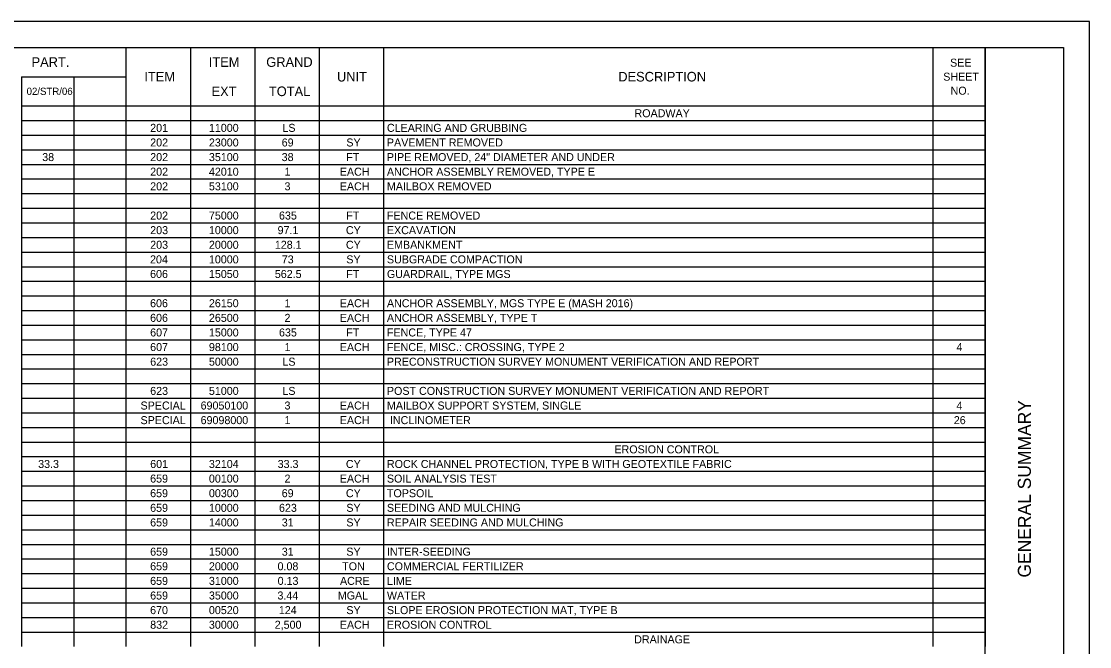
# Model space of a CAD drawing. Extents: x 0 to 34, y 0 to 22.
# Drawn here: x 13.53 to 34, y 10.02 to 22 of the extents above; entities that cross this region are included whole.
import ezdxf

# ---------------------------------------------------------------- set-up
doc = ezdxf.new("R2010")
doc.units = 0
for name, color, linetype in [('Default', 7, 'Continuous'), ('SH_Border', 7, 'Continuous'), ('SH_Cut_Line', 7, 'Continuous'), ('SH_Data', 7, 'Continuous')]:
    doc.layers.add(name, color=color, linetype=linetype)

msp = doc.modelspace()

# ---------------------------------------------------------------- linework, layer by layer
at = {"layer": 'Default'}
for p, q in [((13.53, 21.5), (15.535, 21.5)), ((15.535, 21.5), (32, 21.5)), ((15.535, 21.5), (15.535, 21.22)), ((16.769, 21.5), (16.769, 21.22)), ((18.003, 21.5), (18.003, 21.22)), ((19.237, 21.5), (19.237, 21.22)), ((20.471, 21.5), (20.471, 21.22)), ((30.997, 21.5), (30.997, 21.22)), ((32, 21.5), (32, 21.22)), ((15.535, 21.22), (15.535, 20.94)), ((16.769, 21.22), (16.769, 20.94)), ((18.003, 21.22), (18.003, 20.94)), ((19.237, 21.22), (19.237, 20.94)), ((20.471, 21.22), (20.471, 20.94)), ((30.997, 21.22), (30.997, 20.94)), ((32, 21.22), (32, 20.94)), ((13.53, 20.94), (15.535, 20.94)), ((13.53, 20.94), (13.53, 20.66)), ((14.533, 20.94), (14.533, 20.66)), ((15.535, 20.94), (15.535, 20.66)), ((16.769, 20.94), (16.769, 20.66)), ((18.003, 20.94), (18.003, 20.66)), ((19.237, 20.94), (19.237, 20.66)), ((20.471, 20.94), (20.471, 20.66)), ((30.997, 20.94), (30.997, 20.66)), ((32, 20.94), (32, 20.66)), ((13.53, 20.66), (13.53, 20.38)), ((14.533, 20.66), (14.533, 20.38)), ((15.535, 20.66), (15.535, 20.38)), ((16.769, 20.66), (16.769, 20.38)), ((18.003, 20.66), (18.003, 20.38)), ((19.237, 20.66), (19.237, 20.38)), ((20.471, 20.66), (20.471, 20.38)), ((30.997, 20.66), (30.997, 20.38)), ((32, 20.66), (32, 20.38)), ((13.53, 20.38), (15.535, 20.38)), ((13.53, 20.38), (13.53, 20.1)), ((14.533, 20.38), (14.533, 20.1)), ((15.535, 20.38), (32, 20.38)), ((15.535, 20.38), (15.535, 20.1)), ((16.769, 20.38), (16.769, 20.1)), ((18.003, 20.38), (18.003, 20.1)), ((19.237, 20.38), (19.237, 20.1)), ((20.471, 20.38), (20.471, 20.1)), ((30.997, 20.38), (30.997, 20.1)), ((32, 20.38), (32, 20.1)), ((13.53, 20.1), (15.535, 20.1)), ((13.53, 20.1), (13.53, 18.7)), ((14.533, 20.1), (14.533, 18.7)), ((15.535, 20.1), (32, 20.1)), ((15.535, 20.1), (15.535, 18.7)), ((16.769, 20.1), (16.769, 18.7)), ((18.003, 20.1), (18.003, 18.7)), ((19.237, 20.1), (19.237, 18.7)), ((20.471, 20.1), (20.471, 18.7)), ((30.997, 20.1), (30.997, 18.7)), ((32, 20.1), (32, 18.7)), ((13.53, 19.82), (15.535, 19.82)), ((15.535, 19.82), (32, 19.82)), ((13.53, 19.54), (15.535, 19.54)), ((15.535, 19.54), (32, 19.54)), ((13.53, 19.26), (15.535, 19.26)), ((15.535, 19.26), (32, 19.26)), ((13.53, 18.98), (15.535, 18.98)), ((15.535, 18.98), (32, 18.98)), ((13.53, 18.7), (15.535, 18.7)), ((13.53, 18.7), (13.53, 18.14)), ((14.533, 18.7), (14.533, 18.14)), ((15.535, 18.7), (32, 18.7)), ((15.535, 18.7), (15.535, 18.14)), ((16.769, 18.7), (16.769, 18.14)), ((18.003, 18.7), (18.003, 18.14)), ((19.237, 18.7), (19.237, 18.14)), ((20.471, 18.7), (20.471, 18.14)), ((30.997, 18.7), (30.997, 18.14)), ((32, 18.7), (32, 18.14)), ((13.53, 18.42), (15.535, 18.42)), ((15.535, 18.42), (32, 18.42)), ((13.53, 18.14), (15.535, 18.14)), ((13.53, 18.14), (13.53, 17.86)), ((14.533, 18.14), (14.533, 17.86)), ((15.535, 18.14), (32, 18.14)), ((15.535, 18.14), (15.535, 17.86)), ((16.769, 18.14), (16.769, 17.86)), ((18.003, 18.14), (18.003, 17.86)), ((19.237, 18.14), (19.237, 17.86)), ((20.471, 18.14), (20.471, 17.86)), ((30.997, 18.14), (30.997, 17.86)), ((32, 18.14), (32, 17.86)), ((13.53, 17.86), (15.535, 17.86)), ((13.53, 17.86), (13.53, 17.58)), ((14.533, 17.86), (14.533, 17.58)), ((15.535, 17.86), (32, 17.86)), ((15.535, 17.86), (15.535, 17.58)), ((16.769, 17.86), (16.769, 17.58)), ((18.003, 17.86), (18.003, 17.58)), ((19.237, 17.86), (19.237, 17.58)), ((20.471, 17.86), (20.471, 17.58)), ((30.997, 17.86), (30.997, 17.58)), ((32, 17.86), (32, 17.58)), ((13.53, 17.58), (15.535, 17.58)), ((13.53, 17.58), (13.53, 17.3)), ((14.533, 17.58), (14.533, 17.3)), ((15.535, 17.58), (32, 17.58)), ((15.535, 17.58), (15.535, 17.3)), ((16.769, 17.58), (16.769, 17.3)), ((18.003, 17.58), (18.003, 17.3)), ((19.237, 17.58), (19.237, 17.3)), ((20.471, 17.58), (20.471, 17.3)), ((30.997, 17.58), (30.997, 17.3)), ((32, 17.58), (32, 17.3)), ((13.53, 17.3), (15.535, 17.3)), ((13.53, 17.3), (13.53, 17.02)), ((14.533, 17.3), (14.533, 17.02)), ((15.535, 17.3), (32, 17.3)), ((15.535, 17.3), (15.535, 17.02)), ((16.769, 17.3), (16.769, 17.02)), ((18.003, 17.3), (18.003, 17.02)), ((19.237, 17.3), (19.237, 17.02)), ((20.471, 17.3), (20.471, 17.02)), ((30.997, 17.3), (30.997, 17.02)), ((32, 17.3), (32, 17.02)), ((13.53, 17.02), (15.535, 17.02)), ((13.53, 17.02), (13.53, 16.74)), ((14.533, 17.02), (14.533, 16.74)), ((15.535, 17.02), (32, 17.02)), ((15.535, 17.02), (15.535, 16.74)), ((16.769, 17.02), (16.769, 16.74)), ((18.003, 17.02), (18.003, 16.74)), ((19.237, 17.02), (19.237, 16.74)), ((20.471, 17.02), (20.471, 16.74)), ((30.997, 17.02), (30.997, 16.74)), ((32, 17.02), (32, 16.74)), ((13.53, 16.74), (15.535, 16.74)), ((13.53, 16.74), (13.53, 16.18)), ((14.533, 16.74), (14.533, 16.18)), ((15.535, 16.74), (32, 16.74)), ((15.535, 16.74), (15.535, 16.18)), ((16.769, 16.74), (16.769, 16.18)), ((18.003, 16.74), (18.003, 16.18)), ((19.237, 16.74), (19.237, 16.18)), ((20.471, 16.74), (20.471, 16.18)), ((30.997, 16.74), (30.997, 16.18)), ((32, 16.74), (32, 16.18)), ((13.53, 16.46), (15.535, 16.46)), ((15.535, 16.46), (32, 16.46)), ((13.53, 16.18), (15.535, 16.18)), ((13.53, 16.18), (13.53, 15.9)), ((14.533, 16.18), (14.533, 15.9)), ((15.535, 16.18), (32, 16.18)), ((15.535, 16.18), (15.535, 15.9)), ((16.769, 16.18), (16.769, 15.9)), ((18.003, 16.18), (18.003, 15.9)), ((19.237, 16.18), (19.237, 15.9)), ((20.471, 16.18), (20.471, 15.9)), ((30.997, 16.18), (30.997, 15.9)), ((32, 16.18), (32, 15.9)), ((13.53, 15.9), (15.535, 15.9)), ((13.53, 15.9), (13.53, 15.62)), ((14.533, 15.9), (14.533, 15.62)), ((15.535, 15.9), (32, 15.9)), ((15.535, 15.9), (15.535, 15.62)), ((16.769, 15.9), (16.769, 15.62)), ((18.003, 15.9), (18.003, 15.62)), ((19.237, 15.9), (19.237, 15.62)), ((20.471, 15.9), (20.471, 15.62)), ((30.997, 15.9), (30.997, 15.62)), ((32, 15.9), (32, 15.62)), ((13.53, 15.62), (15.535, 15.62)), ((13.53, 15.62), (13.53, 15.34)), ((14.533, 15.62), (14.533, 15.34)), ((15.535, 15.62), (32, 15.62)), ((15.535, 15.62), (15.535, 15.34)), ((16.769, 15.62), (16.769, 15.34)), ((18.003, 15.62), (18.003, 15.34)), ((19.237, 15.62), (19.237, 15.34)), ((20.471, 15.62), (20.471, 15.34)), ((30.997, 15.62), (30.997, 15.34)), ((32, 15.62), (32, 15.34)), ((13.53, 15.34), (15.535, 15.34)), ((13.53, 15.34), (13.53, 14.78)), ((14.533, 15.34), (14.533, 14.78)), ((15.535, 15.34), (32, 15.34)), ((15.535, 15.34), (15.535, 14.78)), ((16.769, 15.34), (16.769, 14.78)), ((18.003, 15.34), (18.003, 14.78)), ((19.237, 15.34), (19.237, 14.78)), ((20.471, 15.34), (20.471, 14.78)), ((30.997, 15.34), (30.997, 14.78)), ((32, 15.34), (32, 14.78)), ((13.53, 15.06), (15.535, 15.06)), ((15.535, 15.06), (32, 15.06)), ((13.53, 14.78), (15.535, 14.78)), ((13.53, 14.78), (13.53, 14.5)), ((14.533, 14.78), (14.533, 14.5)), ((15.535, 14.78), (32, 14.78)), ((15.535, 14.78), (15.535, 14.5)), ((16.769, 14.78), (16.769, 14.5)), ((18.003, 14.78), (18.003, 14.5)), ((19.237, 14.78), (19.237, 14.5)), ((20.471, 14.78), (20.471, 14.5)), ((30.997, 14.78), (30.997, 14.5)), ((32, 14.78), (32, 14.5)), ((13.53, 14.5), (15.535, 14.5)), ((13.53, 14.5), (13.53, 14.22)), ((14.533, 14.5), (14.533, 14.22)), ((15.535, 14.5), (32, 14.5)), ((15.535, 14.5), (15.535, 14.22)), ((16.769, 14.5), (16.769, 14.22)), ((18.003, 14.5), (18.003, 14.22)), ((19.237, 14.5), (19.237, 14.22)), ((20.471, 14.5), (20.471, 14.22)), ((30.997, 14.5), (30.997, 14.22)), ((32, 14.5), (32, 14.22)), ((13.53, 14.22), (15.535, 14.22)), ((13.53, 14.22), (13.53, 13.94)), ((14.533, 14.22), (14.533, 13.94)), ((15.535, 14.22), (32, 14.22)), ((15.535, 14.22), (15.535, 13.94)), ((16.769, 14.22), (16.769, 13.94)), ((18.003, 14.22), (18.003, 13.94)), ((19.237, 14.22), (19.237, 13.94)), ((20.471, 14.22), (20.471, 13.94)), ((30.997, 14.22), (30.997, 13.94)), ((32, 14.22), (32, 13.94)), ((13.53, 13.94), (15.535, 13.94)), ((13.53, 13.94), (13.53, 11.7)), ((14.533, 13.94), (14.533, 11.7)), ((15.535, 13.94), (32, 13.94)), ((15.535, 13.94), (15.535, 11.7)), ((16.769, 13.94), (16.769, 11.7)), ((18.003, 13.94), (18.003, 11.7)), ((19.237, 13.94), (19.237, 11.7)), ((20.471, 13.94), (20.471, 11.7)), ((30.997, 13.94), (30.997, 11.7)), ((32, 13.94), (32, 11.7)), ((13.53, 13.66), (15.535, 13.66)), ((15.535, 13.66), (32, 13.66)), ((13.53, 13.38), (15.535, 13.38)), ((15.535, 13.38), (32, 13.38)), ((13.53, 13.1), (15.535, 13.1)), ((15.535, 13.1), (32, 13.1)), ((13.53, 12.82), (15.535, 12.82)), ((15.535, 12.82), (32, 12.82)), ((13.53, 12.54), (15.535, 12.54)), ((15.535, 12.54), (32, 12.54)), ((13.53, 12.26), (15.535, 12.26)), ((15.535, 12.26), (32, 12.26)), ((13.53, 11.98), (15.535, 11.98)), ((15.535, 11.98), (32, 11.98)), ((13.53, 11.7), (15.535, 11.7)), ((13.53, 11.7), (13.53, 11.42)), ((14.533, 11.7), (14.533, 11.42)), ((15.535, 11.7), (32, 11.7)), ((15.535, 11.7), (15.535, 11.42)), ((16.769, 11.7), (16.769, 11.42)), ((18.003, 11.7), (18.003, 11.42)), ((19.237, 11.7), (19.237, 11.42)), ((20.471, 11.7), (20.471, 11.42)), ((30.997, 11.7), (30.997, 11.42)), ((32, 11.7), (32, 11.42)), ((13.53, 11.42), (15.535, 11.42)), ((13.53, 11.42), (13.53, 10.3)), ((14.533, 11.42), (14.533, 10.3)), ((15.535, 11.42), (32, 11.42)), ((15.535, 11.42), (15.535, 10.3)), ((16.769, 11.42), (16.769, 10.3)), ((18.003, 11.42), (18.003, 10.3)), ((19.237, 11.42), (19.237, 10.3)), ((20.471, 11.42), (20.471, 10.3)), ((30.997, 11.42), (30.997, 10.3)), ((32, 11.42), (32, 10.3)), ((13.53, 11.14), (15.535, 11.14)), ((15.535, 11.14), (32, 11.14)), ((13.53, 10.86), (15.535, 10.86)), ((15.535, 10.86), (32, 10.86)), ((13.53, 10.58), (15.535, 10.58)), ((15.535, 10.58), (32, 10.58)), ((13.53, 10.3), (15.535, 10.3)), ((13.53, 10.3), (13.53, 10.02)), ((14.533, 10.3), (14.533, 10.02)), ((15.535, 10.3), (32, 10.3)), ((15.535, 10.3), (15.535, 10.02)), ((16.769, 10.3), (16.769, 10.02)), ((18.003, 10.3), (18.003, 10.02)), ((19.237, 10.3), (19.237, 10.02)), ((20.471, 10.3), (20.471, 10.02)), ((30.997, 10.3), (30.997, 10.02)), ((32, 10.3), (32, 10.02))]:
    msp.add_line(p, q, dxfattribs=at)
at = {"layer": 'SH_Border'}
msp.add_line((32, 0.5), (32, 21.5), dxfattribs=at)
msp.add_lwpolyline([(1.5, 21.5), (33.5, 21.5), (33.5, 0.5), (1.5, 0.5)], close=True, dxfattribs=at)
at = {"layer": 'SH_Cut_Line'}
msp.add_lwpolyline([(0, 0), (34, 0), (34, 22), (0, 22)], close=True, dxfattribs=at)

# ---------------------------------------------------------------- texts
at = {"layer": 'Default'}
for s, height, p in [('PART.', 0.184, (13.726, 21.128)), ('ITEM', 0.184, (17.121, 21.128)), ('GRAND', 0.184, (18.223, 21.128)), ('SEE ', 0.1533, (31.326, 21.132)), ('ITEM', 0.184, (15.887, 20.848)), ('UNIT', 0.184, (19.578, 20.848)), ('DESCRIPTION', 0.184, (24.968, 20.848)), ('SHEET ', 0.1533, (31.195, 20.863)), ('02/STR/06', 0.138, (13.631, 20.591)), ('EXT', 0.184, (17.174, 20.568)), ('TOTAL', 0.184, (18.274, 20.568)), ('NO.', 0.1533, (31.336, 20.595)), ('ROADWAY', 0.1533, (25.279, 20.163)), ('201', 0.1533, (15.999, 19.883)), ('11000', 0.1533, (17.124, 19.883)), ('LS', 0.1533, (18.532, 19.883)), ('CLEARING AND GRUBBING', 0.15333, (20.535, 19.883)), ('202', 0.1533, (15.999, 19.603)), ('23000', 0.1533, (17.124, 19.603)), ('69', 0.1533, (18.519, 19.603)), ('SY', 0.1533, (19.757, 19.603)), ('PAVEMENT REMOVED', 0.15333, (20.535, 19.603)), ('38', 0.1533, (13.93, 19.323)), ('202', 0.1533, (15.999, 19.323)), ('35100', 0.1533, (17.124, 19.323)), ('38', 0.1533, (18.518, 19.323)), ('FT', 0.1533, (19.756, 19.323)), ('PIPE REMOVED, 24" DIAMETER AND UNDER', 0.15333, (20.535, 19.323)), ('202', 0.1533, (15.999, 19.043)), ('42010', 0.1533, (17.124, 19.043)), ('1', 0.153, (18.573, 19.043)), ('EACH', 0.1533, (19.632, 19.043)), ('ANCHOR ASSEMBLY REMOVED, TYPE E', 0.15333, (20.535, 19.043)), ('202', 0.1533, (15.999, 18.763)), ('53100', 0.1533, (17.124, 18.763)), ('3', 0.153, (18.573, 18.763)), ('EACH', 0.1533, (19.632, 18.763)), ('MAILBOX REMOVED', 0.15333, (20.535, 18.763)), ('202', 0.1533, (15.999, 18.203)), ('75000', 0.1533, (17.124, 18.203)), ('635', 0.1533, (18.467, 18.203)), ('FT', 0.1533, (19.756, 18.203)), ('FENCE REMOVED', 0.15333, (20.535, 18.203)), ('203', 0.1533, (15.999, 17.923)), ('10000', 0.1533, (17.124, 17.923)), ('97.1', 0.1533, (18.44, 17.923)), ('CY', 0.1533, (19.749, 17.923)), ('EXCAVATION', 0.1533, (20.535, 17.923)), ('203', 0.1533, (15.999, 17.643)), ('20000', 0.1533, (17.124, 17.643)), ('128.1', 0.1533, (18.387, 17.643)), ('CY', 0.1533, (19.749, 17.643)), ('EMBANKMENT', 0.1533, (20.535, 17.643)), ('204', 0.1533, (15.996, 17.363)), ('10000', 0.1533, (17.124, 17.363)), ('73', 0.1533, (18.52, 17.363)), ('SY', 0.1533, (19.757, 17.363)), ('SUBGRADE COMPACTION', 0.15333, (20.535, 17.363)), ('606', 0.1533, (15.997, 17.083)), ('15050', 0.1533, (17.124, 17.083)), ('562.5', 0.1533, (18.387, 17.083)), ('FT', 0.1533, (19.756, 17.083)), ('GUARDRAIL, TYPE MGS', 0.15333, (20.535, 17.083)), ('606', 0.1533, (15.997, 16.523)), ('26150', 0.1533, (17.124, 16.523)), ('1', 0.153, (18.573, 16.523)), ('EACH', 0.1533, (19.632, 16.523)), ('ANCHOR ASSEMBLY, MGS TYPE E (MASH 2016)', 0.15333, (20.535, 16.523)), ('606', 0.1533, (15.997, 16.243)), ('26500', 0.1533, (17.124, 16.243)), ('2', 0.153, (18.573, 16.243)), ('EACH', 0.1533, (19.632, 16.243)), ('ANCHOR ASSEMBLY, TYPE T', 0.15333, (20.535, 16.243)), ('607', 0.1533, (15.998, 15.963)), ('15000', 0.1533, (17.124, 15.963)), ('635', 0.1533, (18.467, 15.963)), ('FT', 0.1533, (19.756, 15.963)), ('FENCE, TYPE 47', 0.15333, (20.535, 15.963)), ('607', 0.1533, (15.998, 15.683)), ('98100', 0.1533, (17.124, 15.683)), ('1', 0.153, (18.573, 15.683)), ('EACH', 0.1533, (19.632, 15.683)), ('FENCE, MISC.: CROSSING, TYPE 2', 0.15333, (20.535, 15.683)), ('4', 0.153, (31.449, 15.683)), ('623', 0.1533, (15.999, 15.403)), ('50000', 0.1533, (17.124, 15.403)), ('LS', 0.1533, (18.532, 15.403)), ('PRECONSTRUCTION SURVEY MONUMENT VERIFICATION AND REPORT', 0.15333, (20.535, 15.403)), ('623', 0.1533, (15.999, 14.843)), ('51000', 0.1533, (17.124, 14.843)), ('LS', 0.1533, (18.532, 14.843)), ('POST CONSTRUCTION SURVEY MONUMENT VERIFICATION AND REPORT', 0.15333, (20.535, 14.843)), ('SPECIAL', 0.1533, (15.814, 14.563)), ('69050100', 0.1533, (16.965, 14.563)), ('3', 0.153, (18.573, 14.563)), ('EACH', 0.1533, (19.632, 14.563)), ('MAILBOX SUPPORT SYSTEM, SINGLE', 0.15333, (20.535, 14.563)), ('4', 0.153, (31.449, 14.563)), ('SPECIAL', 0.1533, (15.814, 14.283)), ('69098000', 0.1533, (16.965, 14.283)), ('1', 0.153, (18.573, 14.283)), ('EACH', 0.1533, (19.632, 14.283)), (' INCLINOMETER', 0.15333, (20.535, 14.283)), ('26', 0.1533, (31.397, 14.283)), ('EROSION CONTROL', 0.15333, (24.894, 13.723)), ('33.3', 0.1533, (13.852, 13.443)), ('601', 0.1533, (15.999, 13.443)), ('32104', 0.1533, (17.124, 13.443)), ('33.3', 0.1533, (18.441, 13.443)), ('CY', 0.1533, (19.749, 13.443)), ('ROCK CHANNEL PROTECTION, TYPE B WITH GEOTEXTILE FABRIC', 0.15333, (20.535, 13.443)), ('659', 0.1533, (15.998, 13.163)), ('00100', 0.1533, (17.124, 13.163)), ('2', 0.153, (18.573, 13.163)), ('EACH', 0.1533, (19.632, 13.163)), ('SOIL ANALYSIS TEST', 0.15333, (20.535, 13.163)), ('659', 0.1533, (15.998, 12.883)), ('00300', 0.1533, (17.124, 12.883)), ('69', 0.1533, (18.519, 12.883)), ('CY', 0.1533, (19.749, 12.883)), ('TOPSOIL', 0.1533, (20.535, 12.883)), ('659', 0.1533, (15.998, 12.603)), ('10000', 0.1533, (17.124, 12.603)), ('623', 0.1533, (18.467, 12.603)), ('SY', 0.1533, (19.757, 12.603)), ('SEEDING AND MULCHING', 0.15333, (20.535, 12.603)), ('659', 0.1533, (15.998, 12.323)), ('14000', 0.1533, (17.124, 12.323)), ('31', 0.1533, (18.52, 12.323)), ('SY', 0.1533, (19.757, 12.323)), ('REPAIR SEEDING AND MULCHING', 0.15333, (20.535, 12.323)), ('659', 0.1533, (15.998, 11.763)), ('15000', 0.1533, (17.124, 11.763)), ('31', 0.1533, (18.52, 11.763)), ('SY', 0.1533, (19.757, 11.763)), ('INTER-SEEDING', 0.15333, (20.535, 11.763)), ('659', 0.1533, (15.998, 11.483)), ('20000', 0.1533, (17.124, 11.483)), ('0.08', 0.1533, (18.439, 11.483)), ('TON', 0.1533, (19.678, 11.483)), ('COMMERCIAL FERTILIZER', 0.15333, (20.535, 11.483)), ('659', 0.1533, (15.998, 11.203)), ('31000', 0.1533, (17.124, 11.203)), ('0.13', 0.1533, (18.441, 11.203)), ('ACRE', 0.1533, (19.636, 11.203)), ('LIME', 0.1533, (20.535, 11.203)), ('659', 0.1533, (15.998, 10.923)), ('35000', 0.1533, (17.124, 10.923)), ('3.44', 0.1533, (18.437, 10.923)), ('MGAL', 0.1533, (19.594, 10.923)), ('WATER', 0.1533, (20.535, 10.923)), ('670', 0.1533, (15.997, 10.643)), ('00520', 0.1533, (17.124, 10.643)), ('124', 0.1533, (18.464, 10.643)), ('SY', 0.1533, (19.757, 10.643)), ('SLOPE EROSION PROTECTION MAT, TYPE B', 0.15333, (20.535, 10.643)), ('832', 0.1533, (15.999, 10.363)), ('30000', 0.1533, (17.124, 10.363)), ('2,500', 0.1533, (18.385, 10.363)), ('EACH', 0.1533, (19.632, 10.363)), ('EROSION CONTROL', 0.15333, (20.535, 10.363)), ('DRAINAGE', 0.1533, (25.273, 10.083))]:
    msp.add_text(s, height=height, dxfattribs=at).set_placement(p)
at = {"layer": 'SH_Data'}
msp.add_text('GENERAL SUMMARY', height=0.25, rotation=90, dxfattribs=at).set_placement((32.875, 11.344))

doc.saveas('drawing.dxf')
